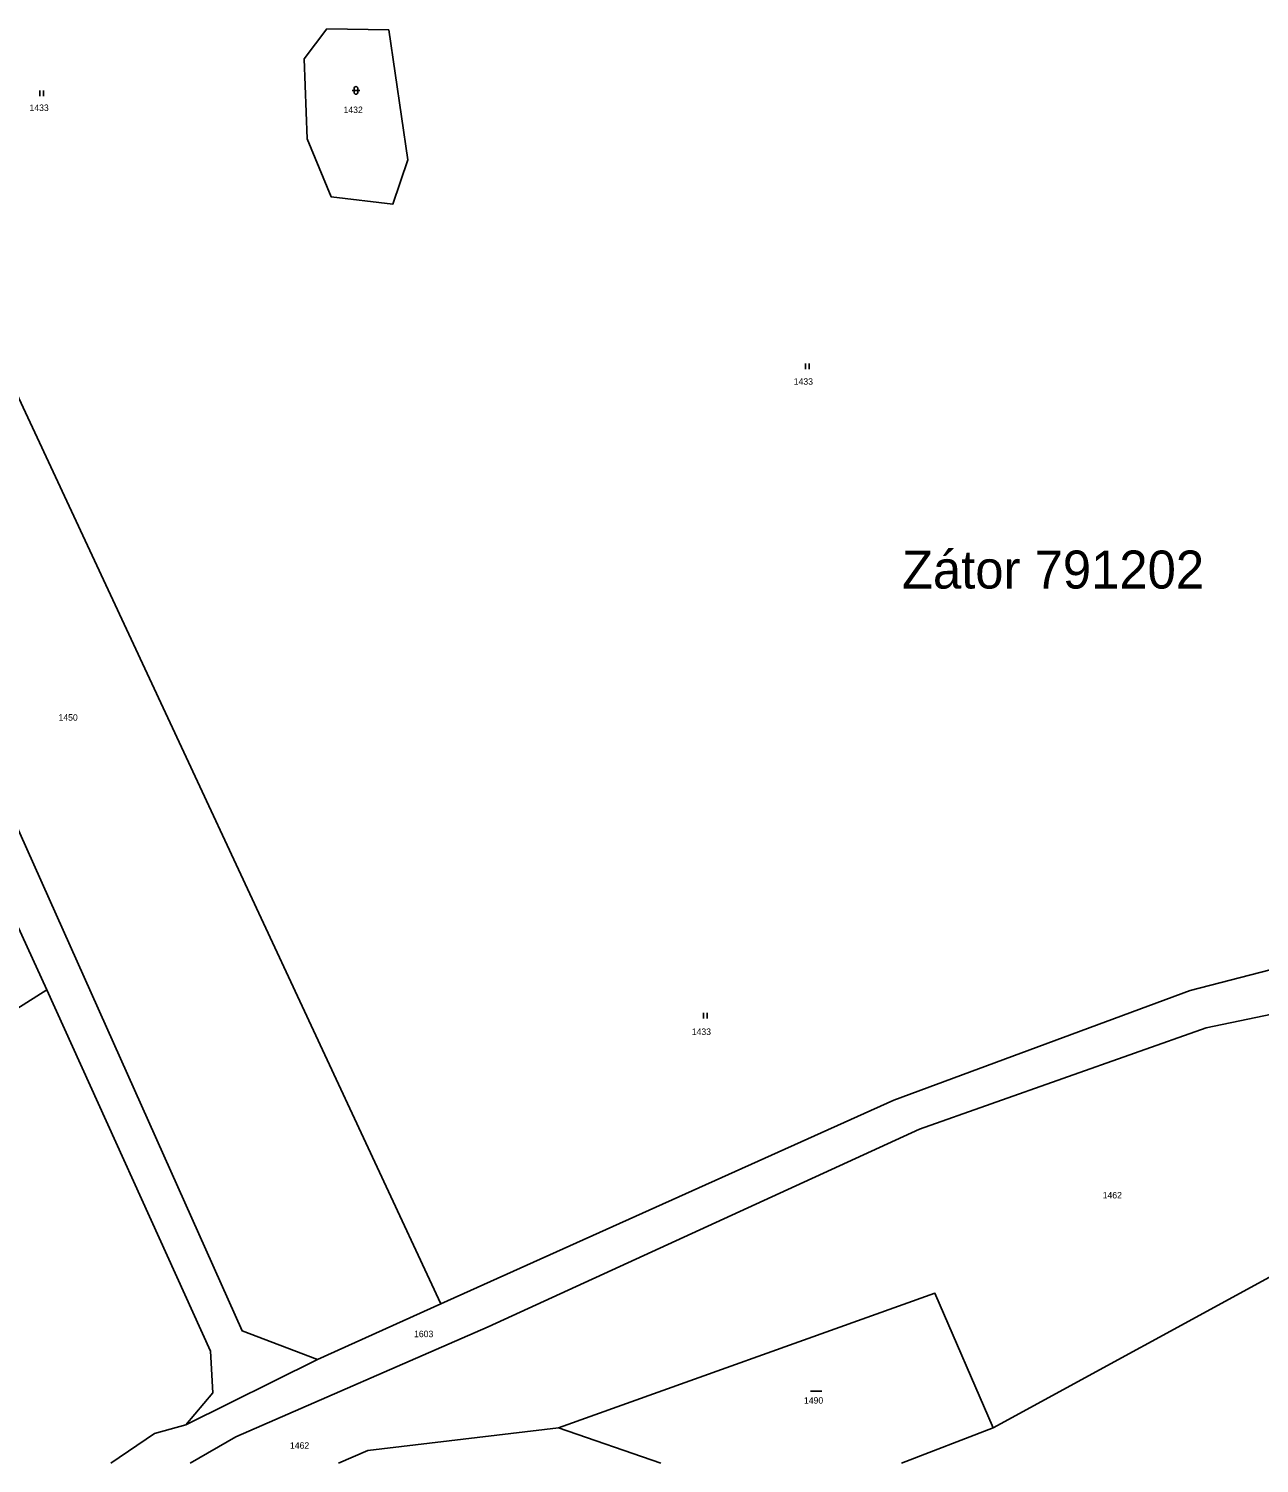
# Model space of a CAD drawing. Extents: x -520431 to -517205, y -1075927 to -1074013.
# Drawn here: x -518648.1 to -518324.2, y -1075925.4 to -1075547.8 of the extents above; entities that cross this region are included whole.
import ezdxf

# ---------------------------------------------------------------- set-up
doc = ezdxf.new("R2010")
doc.units = 0
for name, color, linetype in [('Hranice parcel', 7, 'Continuous'), ('Parcelní čísla', 7, 'Continuous'), ('Pop  PČ popisy', 7, 'Continuous'), ('Značky kultur', 7, 'Continuous')]:
    doc.layers.add(name, color=color, linetype=linetype)

msp = doc.modelspace()

# ---------------------------------------------------------------- linework, layer by layer
at = {"layer": 'Hranice parcel'}
for p, q in [((-518806.25, -1075902.84), (-518643.32, -1075800.78)), ((-518394.26, -1075915.99), (-518309, -1075869.51)), ((-518572.1, -1075898.04), (-518539.62, -1075883.42)), ((-518606.76, -1075915.21), (-518572.1, -1075898.04))]:
    msp.add_line(p, q, dxfattribs=at)
for points in [[(-518553.29, -1075548.11), (-518569.6, -1075547.82), (-518575.6, -1075555.74), (-518574.81, -1075576.82), (-518568.53, -1075592.05), (-518552.27, -1075594.03), (-518548.33, -1075582.3), (-518553.29, -1075548.11)], [(-518687.64, -1075565.98), (-518606.7, -1075739.56), (-518539.62, -1075883.42)], [(-518736.36, -1075574.94), (-518652.28, -1075755.39), (-518591.95, -1075890.51), (-518572.1, -1075898.04)], [(-518643.32, -1075800.78), (-518690.04, -1075698.95), (-518736.77, -1075597.12), (-518742.45, -1075593.22)], [(-518116.8, -1075727.96), (-518208.99, -1075780.87), (-518238.27, -1075795.25), (-518268.25, -1075803.04), (-518309.96, -1075804.85), (-518338.15, -1075810.74), (-518413.65, -1075837.42), (-518527.16, -1075889.45), (-518593.63, -1075918.35), (-518605.58, -1075925.35)], [(-518539.62, -1075883.42), (-518420.38, -1075829.77), (-518342.36, -1075800.93), (-518321.32, -1075795.48), (-518310.89, -1075794.16), (-518279.1, -1075793.91), (-518273.64, -1075790.72), (-518254.06, -1075786.62), (-518247.44, -1075787.39), (-518206.44, -1075767.96), (-518155.35, -1075738.81)], [(-518606.76, -1075915.21), (-518599.68, -1075906.77), (-518600.25, -1075895.84), (-518643.32, -1075800.78)], [(-518394.26, -1075915.99), (-518409.6, -1075880.61), (-518508.63, -1075916.05)], [(-518626.51, -1075925.35), (-518614.98, -1075917.54), (-518606.76, -1075915.21)], [(-518566.54, -1075925.35), (-518558.85, -1075921.97), (-518508.63, -1075916.05)], [(-518508.63, -1075916.05), (-518481.74, -1075925.35)], [(-518418.37, -1075925.35), (-518394.26, -1075915.99)]]:
    msp.add_lwpolyline(points, dxfattribs=at)
at = {"layer": 'Značky kultur'}
for p, q in [((-518645.22, -1075565.62), (-518645.22, -1075564.12)), ((-518644.22, -1075565.62), (-518644.22, -1075564.12)), ((-518562.97, -1075564.05), (-518560.97, -1075564.05)), ((-518562.47, -1075563.55), (-518562.47, -1075564.55)), ((-518561.47, -1075564.55), (-518561.47, -1075563.55)), ((-518443.67, -1075637.45), (-518443.67, -1075635.95)), ((-518442.67, -1075637.45), (-518442.67, -1075635.95)), ((-518470.51, -1075808.32), (-518470.51, -1075806.82)), ((-518469.51, -1075808.32), (-518469.51, -1075806.82)), ((-518442.32, -1075906.36), (-518439.32, -1075906.36))]:
    msp.add_line(p, q, dxfattribs=at)
for centre, start, end in [((-518561.97, -1075563.55), 0, 180), ((-518561.97, -1075564.55), 180, 359.9879)]:
    msp.add_arc(centre, 0.5, start, end, dxfattribs=at)

# ---------------------------------------------------------------- texts
at = {"layer": 'Parcelní čísla'}
for s, p in [('1433', (-518647.9, -1075569.47)), ('1432', (-518565.24, -1075570.01)), ('1433', (-518446.74, -1075641.52)), ('1450', (-518640.26, -1075729.91)), ('1433', (-518473.58, -1075812.63)), ('1462', (-518365.43, -1075855.66)), ('1603', (-518546.68, -1075892.16)), ('1490', (-518444.05, -1075909.66)), ('1462', (-518579.34, -1075921.51))]:
    msp.add_text(s, height=1.7, dxfattribs=at).set_placement(p)
at = {"layer": 'Pop  PČ popisy'}
msp.add_text('Zátor 791202', height=10, dxfattribs=at).set_placement((-518418.28, -1075695.15))

doc.saveas('drawing.dxf')
